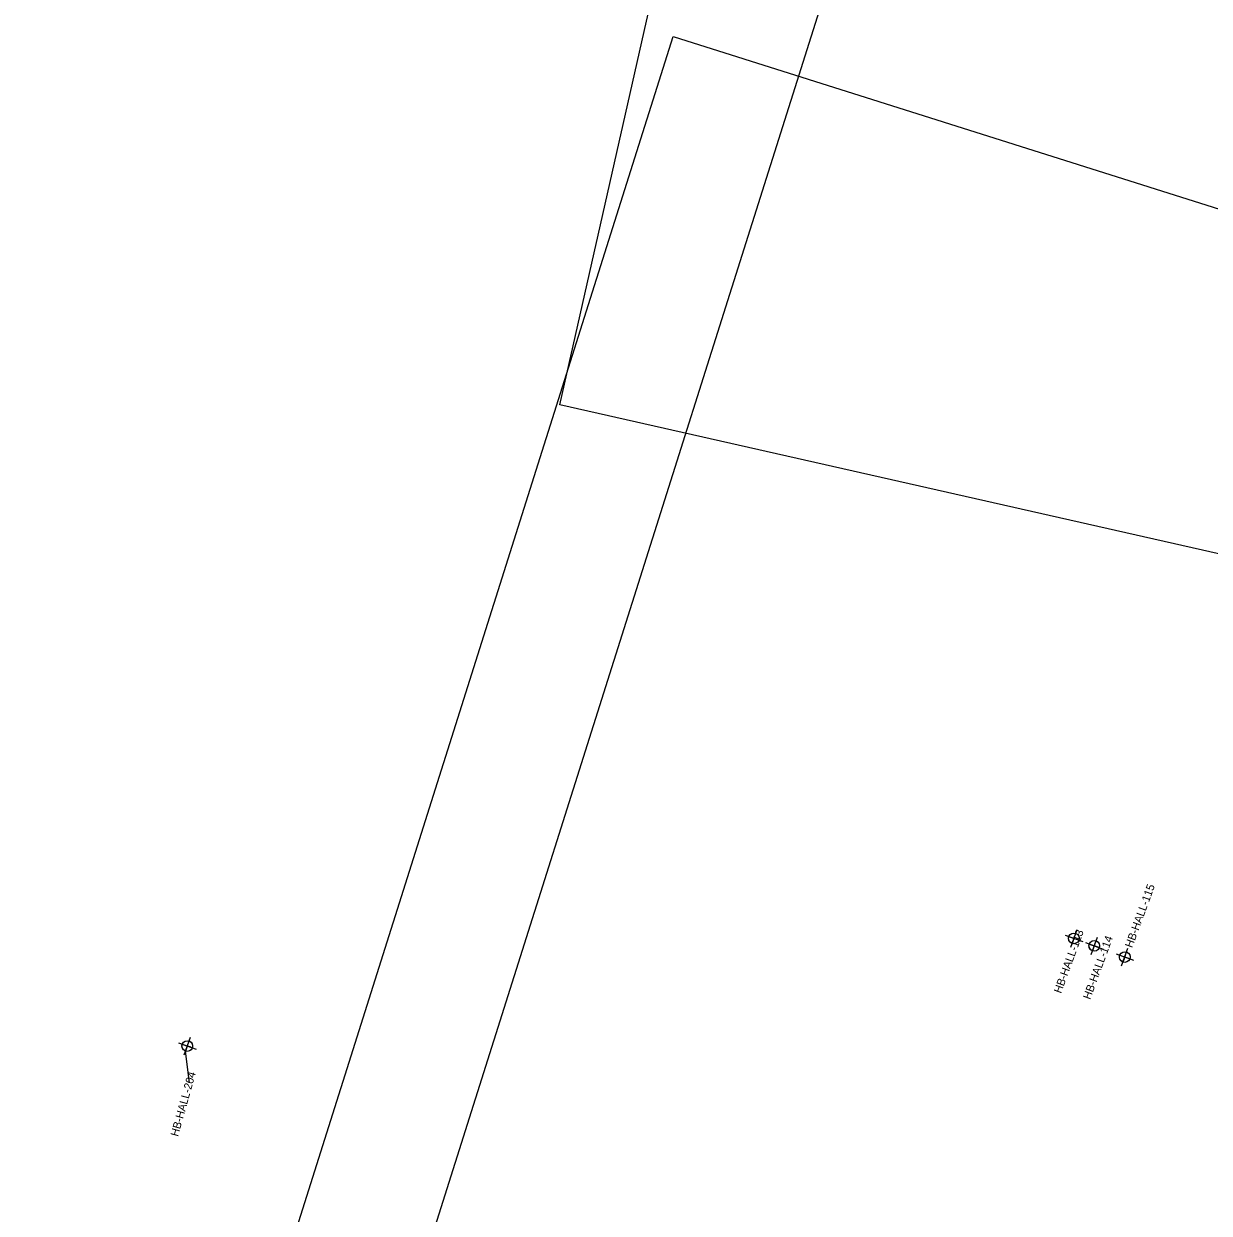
# Model space of a CAD drawing. Extents: x 1136334 to 1137758, y 528745 to 531454.
# Drawn here: x 1136833.5 to 1137271, y 529184.2 to 529623.2 of the extents above; entities that cross this region are included whole.
import ezdxf

# ---------------------------------------------------------------- set-up
doc = ezdxf.new("R2010")
doc.units = 0
for name, color, linetype in [('Default', 7, 'Continuous'), ('PLOT BOUNDARY', 7, 'Continuous'), ('ROCKS', 7, 'Continuous')]:
    doc.layers.add(name, color=color, linetype=linetype)

msp = doc.modelspace()

# ---------------------------------------------------------------- linework, layer by layer
at = {"layer": 'Default'}
msp.add_line((1136894.95, 529245.61), (1136893.8, 529245.93), dxfattribs=at)
at = {"layer": 'PLOT BOUNDARY'}
for points in [[(1137708.64, 530098.42), (1137543.37, 529366.86), (1137031.27, 529482.55), (1137196.54, 530214.11)], [(1137142.07, 529675.56), (1136916.06, 528960.42), (1136415.46, 529118.63), (1136641.47, 529833.77)], [(1137573.8, 529460.37), (1137347.79, 528745.23), (1136847.2, 528903.44), (1137073.21, 529618.57)]]:
    msp.add_lwpolyline(points, close=True, dxfattribs=at)
at = {"layer": 'ROCKS'}
for p, q in [((1137219.92, 529282.42), (1137222.28, 529288.88)), ((1137217.87, 529286.83), (1137224.33, 529284.47)), ((1137225.38, 529284.08), (1137231.84, 529281.72)), ((1137227.43, 529279.67), (1137229.79, 529286.13)), ((1137236.65, 529279.96), (1137243.11, 529277.6)), ((1137238.7, 529275.55), (1137241.06, 529282.01)), ((1136892.62, 529242.7), (1136894.98, 529249.17)), ((1136890.57, 529247.12), (1136897.03, 529244.75)), ((1136894.58, 529232.34), (1136893.12, 529244.09))]:
    msp.add_line(p, q, dxfattribs=at)
for points in [[(1137221.1, 529285.65), (1137221.77, 529287.5), (1137222.02, 529287.38), (1137222.26, 529287.24), (1137222.47, 529287.06), (1137222.68, 529286.83), (1137222.81, 529286.62), (1137222.96, 529286.29), (1137223.02, 529286.06), (1137223.07, 529285.61), (1137223.03, 529285.26), (1137222.95, 529284.97)], [(1137221.1, 529285.65), (1137220.42, 529283.8), (1137220.17, 529283.92), (1137219.94, 529284.06), (1137219.73, 529284.24), (1137219.52, 529284.47), (1137219.38, 529284.68), (1137219.23, 529285.02), (1137219.17, 529285.24), (1137219.13, 529285.69), (1137219.17, 529286.04), (1137219.25, 529286.33)], [(1137228.61, 529282.9), (1137227.93, 529281.05), (1137227.68, 529281.17), (1137227.45, 529281.31), (1137227.24, 529281.49), (1137227.03, 529281.73), (1137226.9, 529281.94), (1137226.75, 529282.27), (1137226.68, 529282.49), (1137226.64, 529282.94), (1137226.68, 529283.29), (1137226.76, 529283.58)], [(1137228.61, 529282.9), (1137229.29, 529284.75), (1137229.54, 529284.64), (1137229.77, 529284.49), (1137229.98, 529284.31), (1137230.19, 529284.08), (1137230.33, 529283.87), (1137230.48, 529283.54), (1137230.54, 529283.31), (1137230.58, 529282.86), (1137230.54, 529282.51), (1137230.46, 529282.23)], [(1137239.88, 529278.78), (1137239.2, 529276.93), (1137238.95, 529277.04), (1137238.72, 529277.19), (1137238.51, 529277.37), (1137238.3, 529277.6), (1137238.16, 529277.81), (1137238.02, 529278.14), (1137237.95, 529278.37), (1137237.91, 529278.82), (1137237.95, 529279.17), (1137238.03, 529279.46)], [(1137239.88, 529278.78), (1137240.56, 529280.63), (1137240.81, 529280.51), (1137241.04, 529280.37), (1137241.25, 529280.19), (1137241.46, 529279.96), (1137241.6, 529279.74), (1137241.74, 529279.41), (1137241.81, 529279.19), (1137241.85, 529278.74), (1137241.81, 529278.39), (1137241.73, 529278.1)], [(1136893.8, 529245.93), (1136894.48, 529247.78), (1136894.73, 529247.67), (1136894.96, 529247.52), (1136895.17, 529247.34), (1136895.38, 529247.11), (1136895.52, 529246.9), (1136895.66, 529246.57), (1136895.73, 529246.35), (1136895.77, 529245.89), (1136895.73, 529245.54), (1136895.65, 529245.26)], [(1136893.8, 529245.93), (1136893.12, 529244.09), (1136892.87, 529244.2), (1136892.64, 529244.35), (1136892.43, 529244.52), (1136892.22, 529244.76), (1136892.08, 529244.97), (1136891.94, 529245.3), (1136891.87, 529245.52), (1136891.83, 529245.98), (1136891.87, 529246.33), (1136891.95, 529246.61)]]:
    msp.add_lwpolyline(points, close=True, dxfattribs=at)
for centre in [(1137221.1, 529285.65), (1137228.61, 529282.9), (1137239.88, 529278.78), (1136893.8, 529245.93)]:
    msp.add_circle(centre, 1.97, dxfattribs=at)

# ---------------------------------------------------------------- texts
for s, rotation, p in [('HB-HALL-115', 69.9054, (1137242.6, 529281.95)), ('HB-HALL-113', 69.9054, (1137216.34, 529265.14)), ('HB-HALL-114', 69.9054, (1137227.11, 529262.88)), ('HB-HALL-204', 74.3343, (1136890.38, 529212.33))]:
    msp.add_text(s, height=2.9528, rotation=rotation, dxfattribs=at).set_placement(p)

doc.saveas('drawing.dxf')
